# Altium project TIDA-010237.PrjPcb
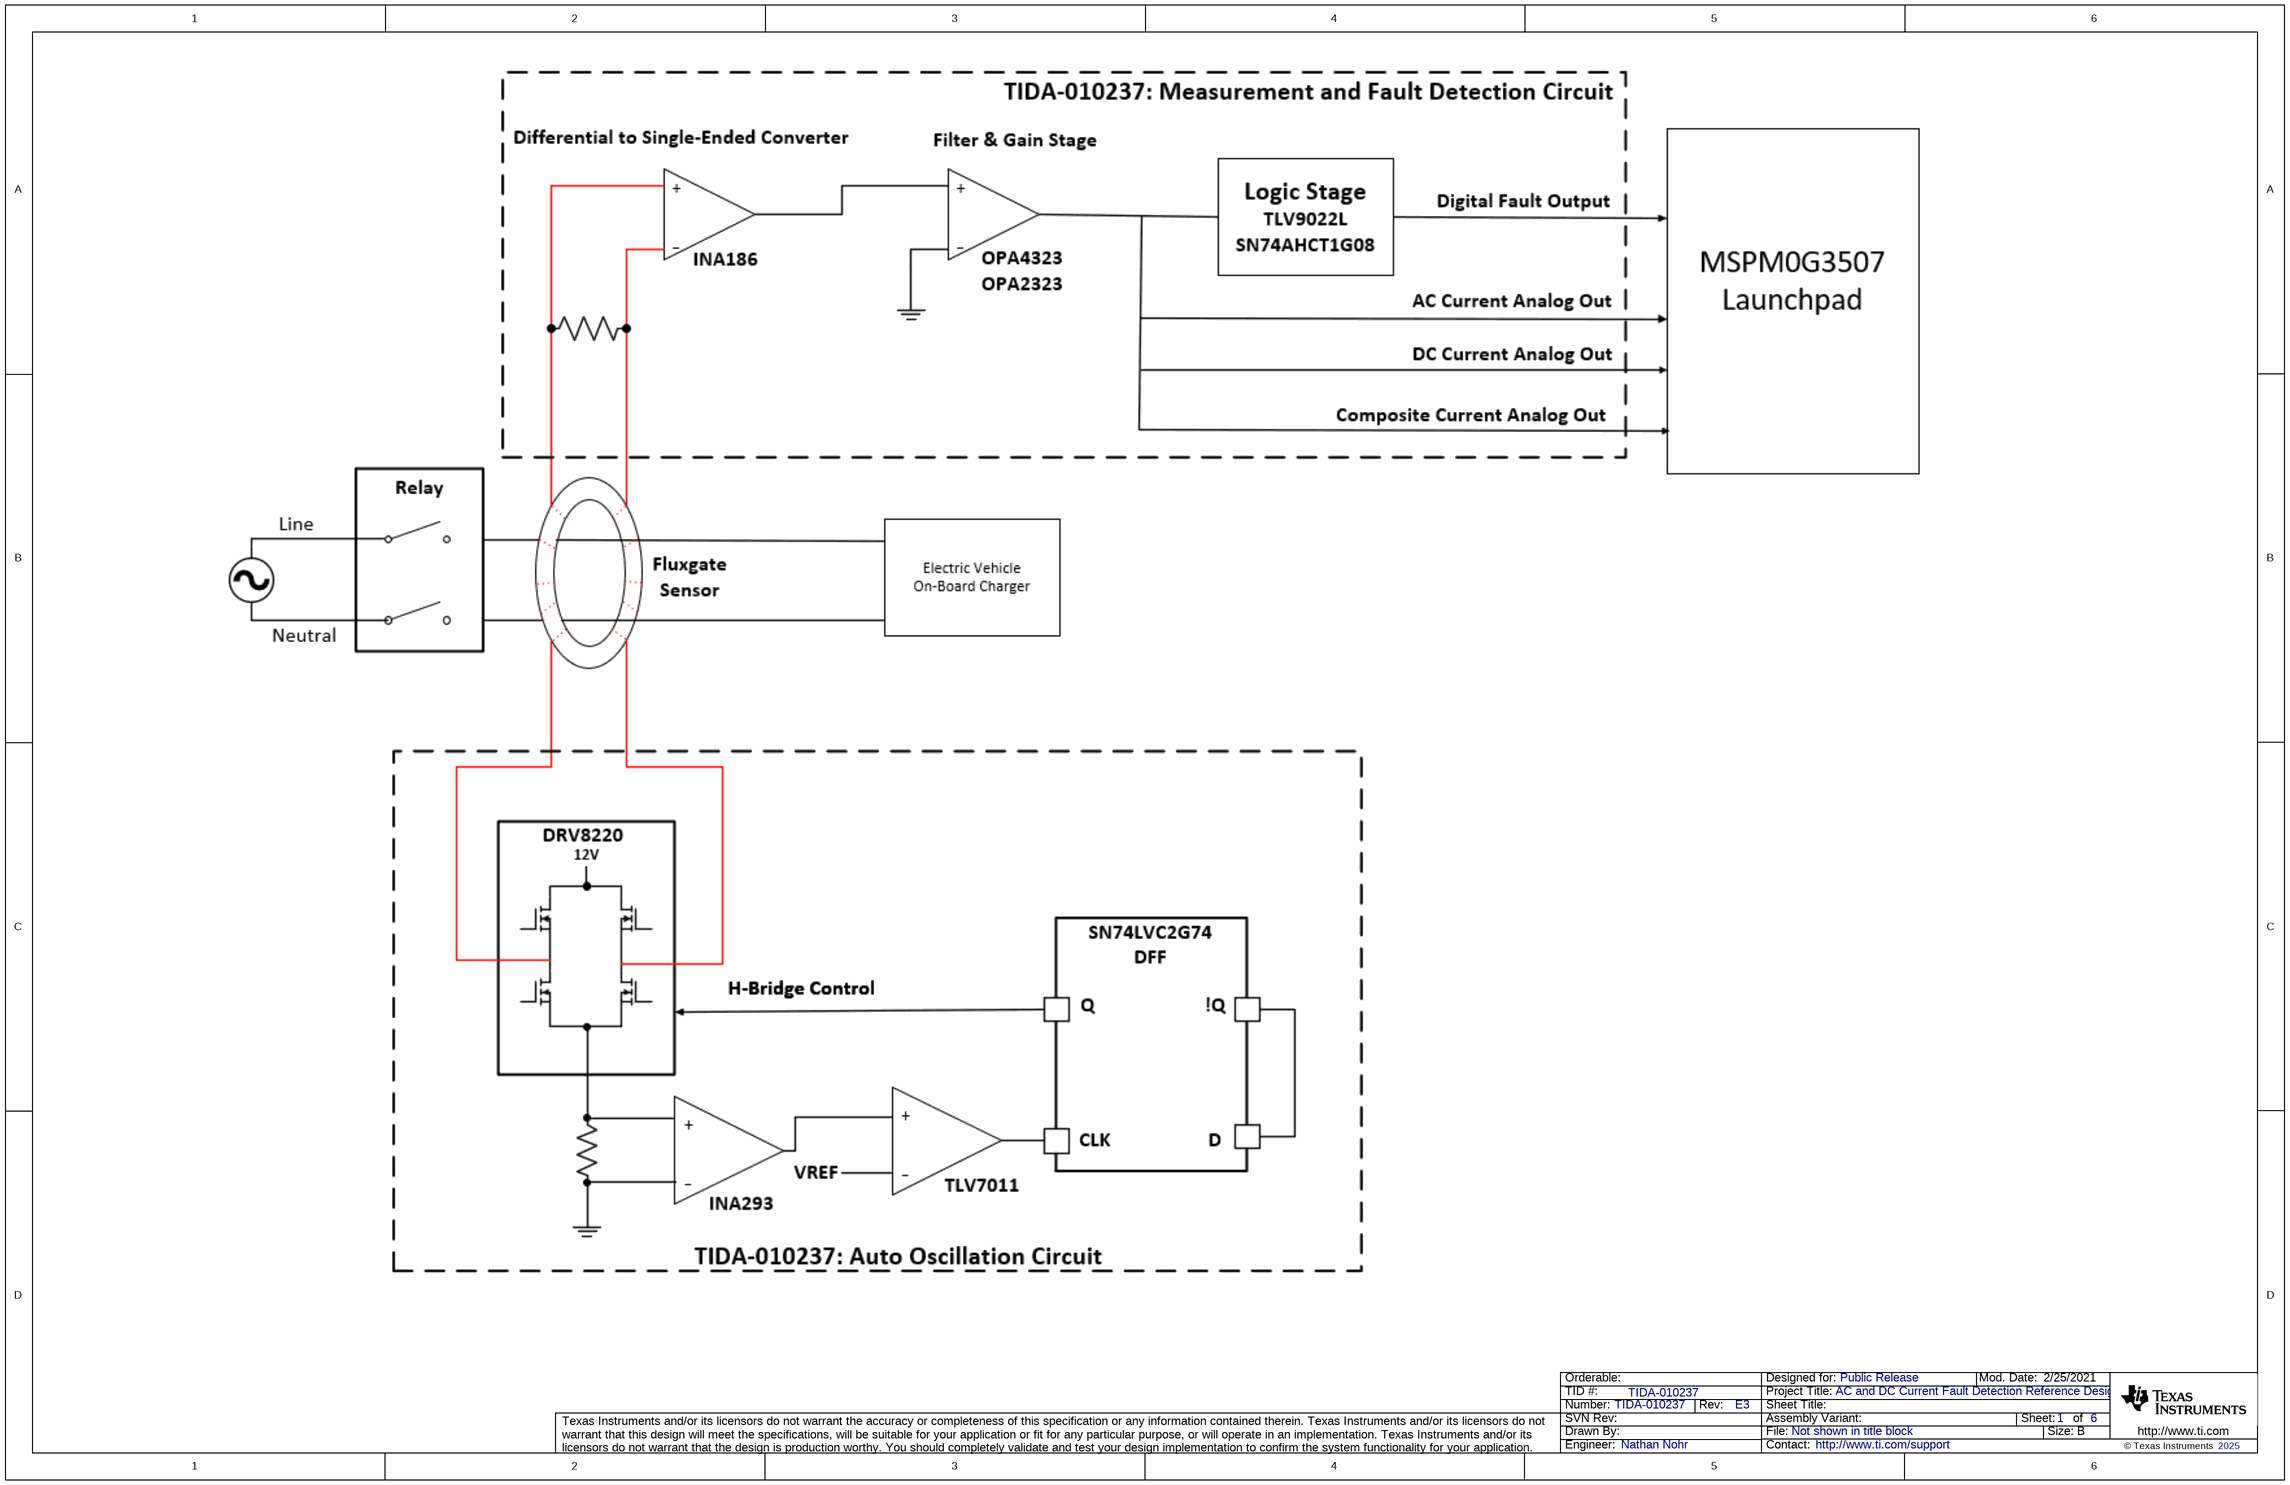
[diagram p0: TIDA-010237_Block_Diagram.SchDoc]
CopyrightYear: 2025; PCB_Layout: Julius Burtell; PCB_Rev: E3; PRJ_Customer: Public Release; PRJ_Engineer: Nathan Nohr; PRJ_Number: TIDA-010237; PRJ_Title: AC and DC Current Fault Detection Reference Design; SCH_Rev: E3; TechSupport: http://www.ti.com/support; TID: TIDA-010237
5 sheets, 144 parts. Net scope: global (net labels, ports and power ports of the same name join across sheets).
Board file: TIDA-010237.PcbDoc
Sheets:
  TIDA-010237_Block_Diagram.SchDoc
  TIDA-010237_Driver_Circuit.SchDoc
  TIDA-010237_Receiver_Circuit.SchDoc
  TIDA-010237_ConnectorsAndPower.SchDoc
  TIDA-010237_Hardware.SchDoc

## Sheet TIDA-010237_Block_Diagram.SchDoc
size 431 x 279 mm; Date: Not shown in title block; ApprovedBy: Not shown in title block; CheckedBy: Not shown in title block; Author: Not shown in title block; CompanyName: Not shown in title block; Engineer: Not shown in title block; Organization: Not shown in title block; Address1: Not shown in title block; Address2: Not shown in title block; Address3: Not shown in title block; Address4: Not shown in title block; DocumentNumber: 1; Revision: Use project parameter SCH_Rev; SheetNumber: 1; SheetTotal: 6; PageSetup: Record=PageOptions¦CenterHorizontal=True¦CenterVertical=True¦PrintScale=1.00¦XCorrection=1.00¦YCorrection=1.00¦PrintKind=0¦BorderSize=5000000¦LeftOffset=0¦BottomOffset=0¦Orientation=2¦PaperLength=1000¦PaperWidth=1000¦Scale=100¦PaperSource=15¦PrintQuality=600¦MediaType=1¦DitherType=10¦PaperKind=Letter¦PrintScaleMode=1

## Sheet TIDA-010237_Driver_Circuit.SchDoc
size 431 x 279 mm; Date: Not shown in title block; ApprovedBy: Not shown in title block; CheckedBy: Not shown in title block; Author: Not shown in title block; CompanyName: Not shown in title block; Engineer: Not shown in title block; Organization: Not shown in title block; Address1: Not shown in title block; Address2: Not shown in title block; Address3: Not shown in title block; Address4: Not shown in title block; DocumentNumber: 2; Revision: Use project parameter SCH_Rev; SheetNumber: 2; SheetTotal: 6; PageSetup: Record=PageOptions¦CenterHorizontal=True¦CenterVertical=True¦PrintScale=1.00¦XCorrection=1.00¦YCorrection=1.00¦PrintKind=0¦BorderSize=5000000¦LeftOffset=0¦BottomOffset=0¦Orientation=2¦PaperLength=1000¦PaperWidth=1000¦Scale=100¦PaperSource=15¦PrintQuality=600¦MediaType=1¦DitherType=10¦PaperKind=Letter¦PrintScaleMode=1
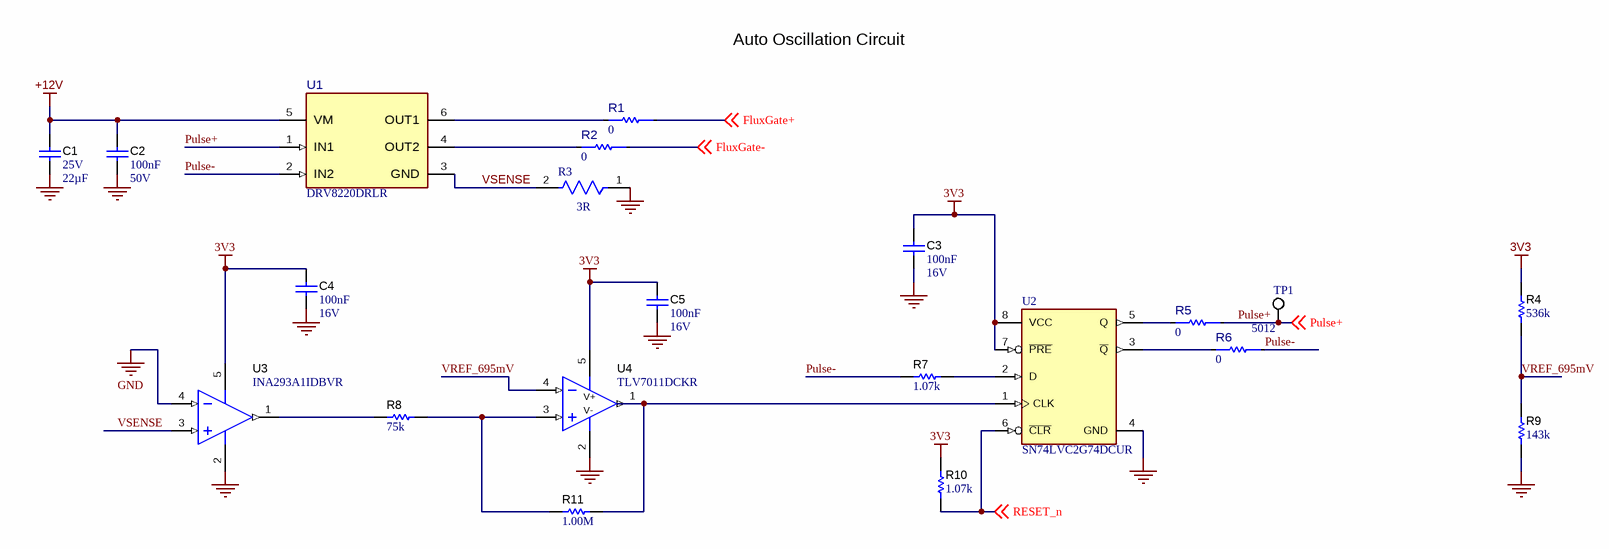
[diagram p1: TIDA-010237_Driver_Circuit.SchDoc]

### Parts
C1  VDC_V: 25V  ValueDisplayed: 22µF  [1210_270]  (hidden comment: CL32B226KAJNFNE)
C2  Cap_F: 100nF  VDC_V: 50V  [0603]  (hidden comment: 06035C104KAZ2A)
C3  Cap_F: 100nF  VDC_V: 16V  [0603]  (hidden comment: EMK107B7104KA-T)
C4  Cap_F: 100nF  VDC_V: 16V  [0603]  (hidden comment: EMK107B7104KA-T)
C5  Cap_F: 100nF  VDC_V: 16V  [0603]  (hidden comment: EMK107B7104KA-T)
R1  value 0  [FP-560112116001_0603-MFG]  (hidden comment: 560112116001)
R2  value 0  [FP-560112116001_0603-MFG]  (hidden comment: 560112116001)
R3  Resistance: 3R  [FP-CRCW1206-e3-IPC_A]  (hidden comment: CRCW12063R00JNEA)
R4  ValueDisplayed: 536k  [0603]  (hidden comment: CRCW0603536KFKEA)
R5  value 0  [FP-560112116001_0603-MFG]  (hidden comment: 560112116001)
R6  value 0  [FP-560112116001_0603-MFG]  (hidden comment: 560112116001)
R7  ValueDisplayed: 1.07k  [0603]  (hidden comment: CRCW06031K07FKEA)
R8  ValueDisplayed: 75k  [0603]  (hidden comment: CRCW060375K0JNEA)
R9  ValueDisplayed: 143k  [0603]  (hidden comment: RC0603FR-07143KL)
R10  ValueDisplayed: 1.07k  [0603]  (hidden comment: CRCW06031K07FKEA)
R11  ValueDisplayed: 1.00M  [0603]  (hidden comment: MCT06030C1004FP500)
TP1  5012  [KSTN-5012_V]
U1  DRV8220DRLR  [DRL0006A-MFG]
U2  SN74LVC2G74DCUR  [FP-DCU0008A-IPC_C]
U3  INA293A1IDBVR  [DBV0005A_M]
U4  TLV7011DCKR  [DCK0005A_N]

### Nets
3V3: C3.1 C4.1 C5.1 R4.2 R10.1 U2.7(~{PRE}) U2.8(VCC) U3.5(V+) U4.5(V+)
+12V: C1.1 C2.1 U1.5(VM)
GND: C1.2 C2.2 C3.2 C4.2 C5.2 R3.1 R9.1 U2.4(GND) U3.2(GND) U3.4(VIN-) U4.2(V-)
FluxGate+: R1.1 ; off-sheet FluxGate+
FluxGate-: R2.1 ; off-sheet FluxGate-
Pulse+: R5.1 TP1.1 U1.1(IN1) ; off-sheet Pulse+
Pulse-: R6.1 R7.1 U1.2(IN2)
RESET_n: R10.2 U2.6(~{CLR}) ; off-sheet RESET_n
VREF_695mV: R4.1 R9.2 U4.4(IN-)
VSENSE: R3.2 U1.3(GND) U3.3(VIN+)
NetR1_2: R1.2 U1.6(OUT1)
NetR2_2: R2.2 U1.4(OUT2)
NetR5_2: R5.2 U2.5(Q)
NetR6_2: R6.2 U2.3(~{Q})
NetR7_2: R7.2 U2.2(D)
NetR8_1: R8.1 U3.1(OUT)
NetR8_2: R8.2 R11.1 U4.3(IN+)
NetR11_2: R11.2 U2.1(CLK) U4.1(OUT)

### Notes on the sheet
- Auto Oscillation Circuit

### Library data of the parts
C1 = CMP-0080066-1: CAP, CERM, 22 µF, 25 V,+/- 10%, X7R, 1210; Manufacturer: Samsung Electro-Mechanics; TaMin_C: -55°C; Polarized: N; SizeAreaWB_mm2: 14.7; U/M: EA; Value: 22uF; TaMax_C: 125°C; SizeZ_mm: 2.7; SizeX_mm: 3.2; SizeY_mm: 2.5; Cap_Case: 1210; SizeArea_mm2: 8; AEC Category: Q200
C2 = CMP-0079095-1: CAP, CERM, 0.1 µF, 50 V,+/- 10%, X7R, AEC-Q200 Grade 1, 0603; Manufacturer: AVX; SizeAreaWB_mm2: 4.68; SizeArea_mm2: 1.28; AEC Qualified: Y; AEC Category: Q200; Value: 0.1uF; TaMax_C: 125°C; SizeZ_mm: 1; Polarized: N; TaMin_C: -55°C; SizeY_mm: 0.8; U/M: EA; SizeX_mm: 1.6; ValueDisplayed: 0.1µF
C3-C5 = CMP-0007119-4: CAP, CERM, 0.1 uF, 16 V, +/- 10%, X7R, 0603; Manufacturer: Taiyo Yuden; TaMin_C: -55°C; Polarized: N; SizeAreaWB_mm2: 4.68; Value1: Unknown; U/M: EA; Value: 0.1uF; TaMax_C: 125°C; SizeZ_mm: 1; SizeX_mm: 1.6; SizeY_mm: 0.8; SizeArea_mm2: 1.28; AEC Category: Q200
R1 R2 R5 R6 = CMP-0125813-1: 0 Ohms Jumper Chip Resistor 0603 (1608 Metric) Anti-Sulfur Thick Film; Manufacturer: Wurth Electronics; AEC Qualified: No; Power_W: 100mW; SizeZ_mm: 0.6mm; Max Current: 1A
R3 = CMP-1014-00013-3: RES Thick Film, 3Ω, 5%, 0.25W, 200ppm/°C, 1206; Voltage Rating (DC): 200V; Power Rating: 250mW
R4 = CMP-0022488-1: RES, 536 k, 1%, 0.1 W, 0603; Manufacturer: Vishay-Dale; Power_W: 100mW; TempCo: 100 ppm/C; U/M: EA; Value: 536k; EIA_Code: E96; SizeX_mm: 1.6; SizeY_mm: 0.8; SizeZ_mm: 1; Value2: 0.1W; SizeArea_mm2: 1.28; VDC_V: 75V; AEC Category: Q200
R7 R10 = CMP-0022112-4: RES, 1.07 k, 1%, 0.1 W, AEC-Q200 Grade 0, 0603; Manufacturer: Vishay-Dale; Power_W: 100mW; TempCo: 100 ppm/C; Value_Code: 1k07; Value: 1.07k; EIA_Code: E96; SizeX_mm: 1.6; SizeY_mm: 0.8; SizeZ_mm: 1; Value2: 0.1W; SizeArea_mm2: 1.28; AEC Qualified: Y; VDC_V: 75V; AEC Category: Q200; AEC Grade: 0
R8 = CMP-0025853-1: RES, 75 k, 5%, 0.1 W, 0603; Manufacturer: Vishay-Dale; Power_W: 100mW; TempCo: 200 ppm/C; Value_Code: 75k0; U/M: EA; Value: 75k; EIA_Code: E24; SizeX_mm: 1.6; SizeY_mm: 0.8; SizeZ_mm: 1; Value2: 0.1W; SizeArea_mm2: 1.28; VDC_V: 75V; AEC Category: Q200
R9 = CMP-0022798-4: RES, 143 k, 1%, 0.1 W, 0603; Manufacturer: Yageo; Power_W: 100mW; TempCo: 100 ppm/C; Value: 143k; EIA_Code: E96; SizeX_mm: 1.6; SizeY_mm: 0.8; SizeZ_mm: 1; Value2: 0.1W; SizeArea_mm2: 1.28; AEC Qualified: N; VDC_V: 75V; AEC Category: Q200; SizeAreaWB_mm2: 4.68
R11 = CMP-0022731-2: RES, 1.00 M, 1%, 0.125 W, 0603; Manufacturer: Vishay/Beyschlag; Power_W: 125mW; TempCo: 50 ppm/C; Value_Code: 1M00; U/M: EA; Value: 1.00Meg; EIA_Code: E96; Res_ohm: 1M; SizeX_mm: 1.6; SizeY_mm: 0.8; SizeZ_mm: 1; Value2: 0.125W; SizeArea_mm2: 1.28; AEC Qualified: N; VDC_V: 75V; AEC Category: Q200
TP1 = CMP-1672-00004-3: Test Point, White, Through Hole, RoHS, Bulk
U1 = CMP-0090278-3: 18V, 1A H-bridge motor driver, PWM, PH/EN, ½ bridge control, with low power sleep mode; Manufacturer: Texas Instruments; TaMax_C: +125°C; Min Supply Voltage: 4.5V; Number Of Outputs: 2; AEC Category: Q200; AEC Qualified: No; SizeZ_mm: 0.6mm; TaMin_C: -40°C; Motor Type: Brushed; CompType: IC; Switching Frequency: 100kHz; Standoff Height: 0mm; TJmax_C: +150°C
U2 = CMP-0859-00648-4: IC FF D-TYPE SNGL 1BIT US8; Manufacturer: Texas Instruments; Frequency: 140MHz; Standoff Height: 0mm; Propagation Delay: 6.1ns; Logic Function Desc: D Type; Number Of Outputs: 2; Nominal Supply Current: 10uA; Max Supply Voltage: 5.5V; Number Of Inputs: 1; Min Supply Voltage: 1.65V
U3 = CMP-0750213-2: INA293 High-Voltage, High Bandwidth, Unidirectional, 110-V Common-Mode, Current-Sense Amplifier, DBV0005A (SOT-23-5); Alternate Manufacturer: Texas Instruments; Alternate PartNumber: INA293A1IDBVT; SizeZ_mm: 1.45; AEC Qualified: N; CompType: IC; SizeAreaWB_mm2: 14.82; SizeArea_mm2: 8.12; SizeY_mm: 2.9; AEC Category: Q200; SizeX_mm: 2.8
U4 = CMP-0860894-1: Low power, small size comparator with push-pull output, DCK0005A (SOT-SC70-5); Alternate Manufacturer: Texas Instruments; Alternate PartNumber: TLV7011DCKT; CompType: IC; SizeZ_mm: 1.1; SizeY_mm: 2; AEC Qualified: N; AEC Category: Q200; SizeX_mm: 2.1; SizeAreaWB_mm2: 9.3; SizeArea_mm2: 4.2; Rating: Catalog

## Sheet TIDA-010237_Receiver_Circuit.SchDoc
size 431 x 279 mm; Date: Not shown in title block; ApprovedBy: Not shown in title block; CheckedBy: Not shown in title block; Author: Not shown in title block; CompanyName: Not shown in title block; Engineer: Not shown in title block; Organization: Not shown in title block; Address1: Not shown in title block; Address2: Not shown in title block; Address3: Not shown in title block; Address4: Not shown in title block; DocumentNumber: 3; Revision: Use project parameter SCH_Rev; SheetNumber: 3; SheetTotal: 6; PageSetup: Record=PageOptions¦CenterHorizontal=True¦CenterVertical=True¦PrintScale=1.00¦XCorrection=1.00¦YCorrection=1.00¦PrintKind=0¦BorderSize=5000000¦LeftOffset=0¦BottomOffset=0¦Orientation=2¦PaperLength=1000¦PaperWidth=1000¦Scale=100¦PaperSource=15¦PrintQuality=600¦MediaType=1¦DitherType=10¦PaperKind=Letter¦PrintScaleMode=1
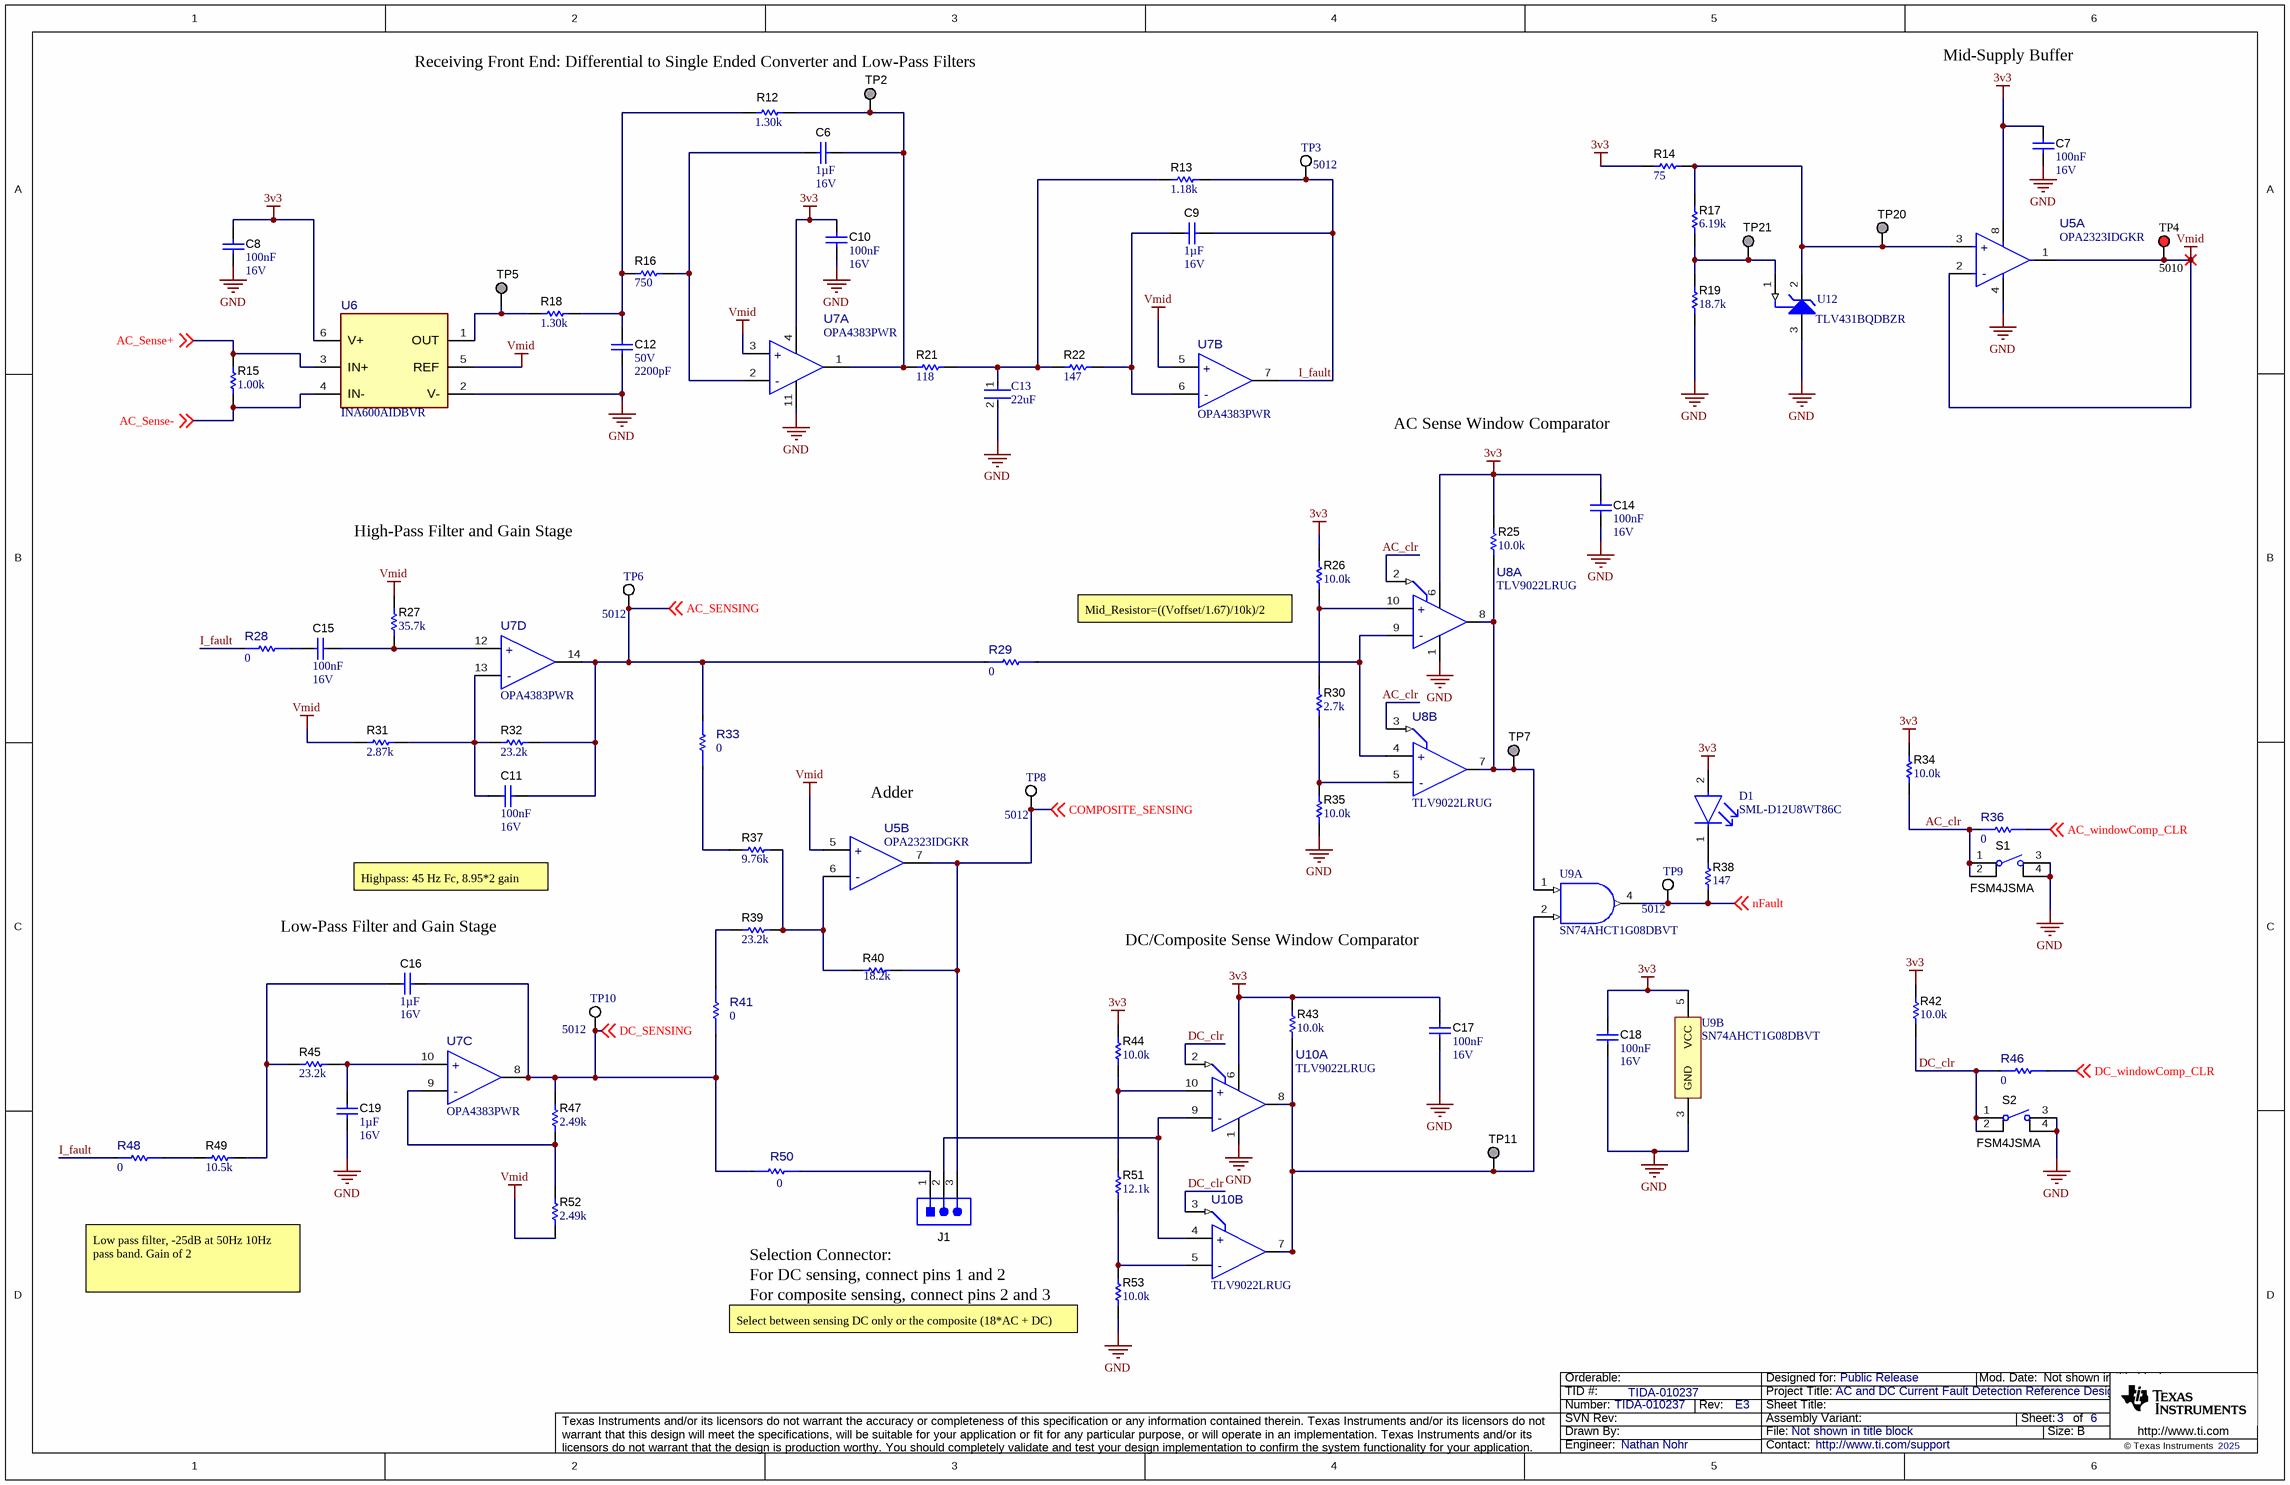
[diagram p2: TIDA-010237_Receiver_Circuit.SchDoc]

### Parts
C6  Cap_F: 1µF  VDC_V: 16V  [0603]  (hidden comment: EMK107B7105KAHT)
C7  Cap_F: 100nF  VDC_V: 16V  [0603]  (hidden comment: EMK107B7104KA-T)
C8  Cap_F: 100nF  VDC_V: 16V  [0603]  (hidden comment: EMK107B7104KA-T)
C9  Cap_F: 1µF  VDC_V: 16V  [0603]  (hidden comment: EMK107B7105KAHT)
C10  Cap_F: 100nF  VDC_V: 16V  [0603]  (hidden comment: EMK107B7104KA-T)
C11  Cap_F: 100nF  VDC_V: 16V  [0603]  (hidden comment: EMK107B7104KA-T)
C12  VDC_V: 50V  ValueDisplayed: 2200pF  [0603]  (hidden comment: GRM1885C1H222JA01D)
C13  Capacitance: 22uF  [FP-1206-L_3_2_0_2-W_1_6_0-IPC_C]  (hidden comment: 1206YD226KAT2A)
C14  Cap_F: 100nF  VDC_V: 16V  [0603]  (hidden comment: EMK107B7104KA-T)
C15  Cap_F: 100nF  VDC_V: 16V  [0603]  (hidden comment: EMK107B7104KA-T)
C16  Cap_F: 1µF  VDC_V: 16V  [0603]  (hidden comment: EMK107B7105KAHT)
C17  Cap_F: 100nF  VDC_V: 16V  [0603]  (hidden comment: EMK107B7104KA-T)
C18  Cap_F: 100nF  VDC_V: 16V  [0603]  (hidden comment: EMK107B7104KA-T)
C19  Cap_F: 1µF  VDC_V: 16V  [0603]  (hidden comment: EMK107B7105KAHT)
D1  SML-D12U8WT86C  [FP-SML-D12-MFG]
J1  PEC03SAAN  [CONN_PEC03SAAN]  (value not drawn)
R12  ValueDisplayed: 1.30k  [0603]  (hidden comment: RC0603FR-071K3L)
R13  ValueDisplayed: 1.18k  [0603]  (hidden comment: CRCW06031K18FKEA)
R14  ValueDisplayed: 75  [0603]  (hidden comment: CRCW060375R0JNEA)
R15  ValueDisplayed: 1.00k  [0603]  (hidden comment: ERA3AEB102V)
R16  ValueDisplayed: 750  [0603]  (hidden comment: CRCW0603750RFKEA)
R17  ValueDisplayed: 6.19k  [0603]  (hidden comment: RT0603BRD076K19L)
R18  ValueDisplayed: 1.30k  [0603]  (hidden comment: RC0603FR-071K3L)
R19  ValueDisplayed: 18.7k  [0603]  (hidden comment: RT0603BRD0718K7L)
R21  ValueDisplayed: 118  [0603]  (hidden comment: RC0603FR-07118RL)
R22  ValueDisplayed: 147  [0603]  (hidden comment: RC0603FR-07147RL)
R25  ValueDisplayed: 10.0k  [0603]  (hidden comment: RC0603FR-0710KL)
R26  ValueDisplayed: 10.0k  [0603]  (hidden comment: RC0603FR-0710KL)
R27  ValueDisplayed: 35.7k  [0603]  (hidden comment: RC0603FR-0735K7L)
R28  value 0  [FP-560112116001_0603-MFG]  (hidden comment: 560112116001)
R29  value 0  [FP-560112116001_0603-MFG]  (hidden comment: 560112116001)
R30  ValueDisplayed: 2.7k  [0603]  (hidden comment: RC0603JR-072K7L)
R31  ValueDisplayed: 2.87k  [0603]  (hidden comment: RC0603FR-072K87L)
R32  ValueDisplayed: 23.2k  [0603]  (hidden comment: CRCW060323K2FKEA)
R33  value 0  [FP-560112116001_0603-MFG]  (hidden comment: 560112116001)
R34  ValueDisplayed: 10.0k  [0603]  (hidden comment: RC0603FR-0710KL)
R35  ValueDisplayed: 10.0k  [0603]  (hidden comment: RC0603FR-0710KL)
R36  value 0  [FP-560112116001_0603-MFG]  (hidden comment: 560112116001)
R37  ValueDisplayed: 9.76k  [0603]  (hidden comment: RC0603FR-079K76L)
R38  ValueDisplayed: 147  [0603]  (hidden comment: RC0603FR-07147RL)
R39  ValueDisplayed: 23.2k  [0603]  (hidden comment: CRCW060323K2FKEA)
R40  ValueDisplayed: 18.2k  [0603]  (hidden comment: RT0603DRE0718K2L)
R41  value 0  [FP-560112116001_0603-MFG]  (hidden comment: 560112116001)
R42  ValueDisplayed: 10.0k  [0603]  (hidden comment: RC0603FR-0710KL)
R43  ValueDisplayed: 10.0k  [0603]  (hidden comment: RC0603FR-0710KL)
R44  ValueDisplayed: 10.0k  [0603]  (hidden comment: RC0603FR-0710KL)
R45  ValueDisplayed: 23.2k  [0603]  (hidden comment: CRCW060323K2FKEA)
R46  value 0  [FP-560112116001_0603-MFG]  (hidden comment: 560112116001)
R47  ValueDisplayed: 2.49k  [0603]  (hidden comment: CRCW06032K49FKEA)
R48  value 0  [FP-560112116001_0603-MFG]  (hidden comment: 560112116001)
R49  ValueDisplayed: 10.5k  [0603]  (hidden comment: CRCW060310K5FKEA)
R50  value 0  [FP-560112116001_0603-MFG]  (hidden comment: 560112116001)
R51  ValueDisplayed: 12.1k  [0603]  (hidden comment: RT0603DRE0712K1L)
R52  ValueDisplayed: 2.49k  [0603]  (hidden comment: CRCW06032K49FKEA)
R53  ValueDisplayed: 10.0k  [0603]  (hidden comment: RC0603FR-0710KL)
S1  FSM4JSMA  [SW_FSM4JSMA]
S2  FSM4JSMA  [SW_FSM4JSMA]
TP2  TP_SM_1MM  [TP_SM_1MM]  (value not drawn)  (no BOM)
TP3  5012  [KSTN-5012_V]
TP4  5010  [KSTN-5010_V]
TP5  TP_SM_1MM  [TP_SM_1MM]  (value not drawn)  (no BOM)
TP6  5012  [KSTN-5012_V]
TP7  TP_SM_1MM  [TP_SM_1MM]  (value not drawn)  (no BOM)
TP8  5012  [KSTN-5012_V]
TP9  5012  [KSTN-5012_V]
TP10  5012  [KSTN-5012_V]
TP11  TP_SM_1MM  [TP_SM_1MM]  (value not drawn)  (no BOM)
TP20  TP_SM_1MM  [TP_SM_1MM]  (value not drawn)  (no BOM)
TP21  TP_SM_1MM  [TP_SM_1MM]  (value not drawn)  (no BOM)
U5  OPA2323IDGKR  [DGK0008A-MFG]  (parts A,B of 2)
U6  INA600AIDBVR  [DBV0006A-MFG]
U7  OPA4383PWR  [PW0014A-MFG]  (parts A,B,C,D of 4)
U8  TLV9022LRUG  [RUG0010A-MFG]  (parts A,B of 2)
U9  SN74AHCT1G08DBVT  [DBV0005A_N]  (parts A,B of 2)
U10  TLV9022LRUG  [RUG0010A-MFG]  (parts A,B of 2)
U12  TLV431BQDBZR  [DBZ0003A_N]

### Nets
3V3: C7.1 C8.1 C10.1 C14.1 C17.1 C18.1 D1.2(A) R14.1 R25.1 R26.1 R34.1 R42.1 R43.1 R44.1 U5.8(V+) U6.6(V+) U7.4(V+) U8.6(V+) U9.5(VCC) U10.6(V+)
GND: C7.2 C8.2 C10.2 C12.2 C13.2 C14.2 C17.2 C18.2 C19.2 R19.1 R35.2 R53.2 S1.3 S1.4 S2.3 S2.4 U5.4(V-) U6.2(V-) U7.11(V-) U8.1(V-) U9.3(GND) U10.1(V-) U12.3(ANODE)
Vmid: R27.2 R31.1 R52.1 TP4.1 U5.1(OUT1) U5.2(IN1-) U5.5(IN2+) U6.5(REF) U7.3(+IN_A) U7.5(+IN_B)
AC_clr: R34.2 R36.2 S1.1 S1.2 U8.2(CLR_A) U8.3(CLR_B)
AC_Sense+: R15.2 U6.3(IN+) ; off-sheet AC_Sense+
AC_Sense-: R15.1 U6.4(IN-) ; off-sheet AC_Sense-
AC_SENSING: C11.2 R29.2 R32.2 R33.2 TP6.1 U7.14(OUT_D) ; off-sheet AC_SENSING
AC_windowComp_CLR: R36.1 ; off-sheet AC_windowComp_CLR
COMPOSITE_SENSING: J1.3 R40.2 TP8.1 U5.7(OUT2) ; off-sheet COMPOSITE_SENSING
DC_clr: R42.2 R46.2 S2.1 S2.2 U10.2(CLR_A) U10.3(CLR_B)
DC_SENSING: C16.2 R41.1 R47.2 R50.2 TP10.1 U7.8(OUT_C) ; off-sheet DC_SENSING
DC_windowComp_CLR: R46.1 ; off-sheet DC_windowComp_CLR
I_fault: C9.1 R13.2 R28.2 R48.2 TP3.1 U7.7(OUT_B)
nFault: R38.1 TP9.1 U9.4(Y) ; off-sheet nFault
NetC6_1: C6.1 R12.2 R21.1 TP2.1 U7.1(OUT_A)
NetC6_2: C6.2 R16.2 U7.2(-IN_A)
NetC9_2: C9.2 R22.2 U7.6(-IN_B)
NetC11_1: C11.1 R31.2 R32.1 U7.13(-IN_D)
NetC12_1: C12.1 R12.1 R16.1 R18.2
NetC13_1: C13.1 R13.1 R21.2 R22.1
NetC15_1: C15.1 R27.1 U7.12(+IN_D)
NetC15_2: C15.2 R28.1
NetC16_1: C16.1 R45.1 R49.2
NetC19_1: C19.1 R45.2 U7.10(+IN_C)
NetD1_1: D1.1(C) R38.2
NetJ1_1: J1.1 R50.1
NetJ1_2: J1.2 U10.4(IN+_B) U10.9(IN-_A)
NetR14_2: R14.2 R17.2 TP20.1 U5.3(IN1+) U12.2(CATHODE)
NetR17_1: R17.1 R19.2 TP21.1 U12.1(REF)
NetR18_1: R18.1 TP5.1 U6.1(OUT)
NetR25_2: R25.2 TP7.1 U8.7(OUT_B) U8.8(OUT_A) U9.1(A)
NetR26_2: R26.2 R30.2 U8.10(IN+_A)
NetR29_1: R29.1 U8.4(IN+_B) U8.9(IN-_A)
NetR30_1: R30.1 R35.1 U8.5(IN-_B)
NetR33_1: R33.1 R37.1
NetR37_2: R37.2 R39.2 R40.1 U5.6(IN2-)
NetR39_1: R39.1 R41.2
NetR43_2: R43.2 TP11.1 U9.2(B) U10.7(OUT_B) U10.8(OUT_A)
NetR44_2: R44.2 R51.2 U10.10(IN+_A)
NetR47_1: R47.1 R52.2 U7.9(-IN_C)
NetR48_1: R48.1 R49.1
NetR51_1: R51.1 R53.1 U10.5(IN-_B)

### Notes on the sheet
- Receiving Front End: Differential to Single Ended Converter and Low-Pass Filters
- Mid-Supply Buffer
- AC Sense Window Comparator
- High-Pass Filter and Gain Stage
- (near R26) Mid_Resistor=((Voffset/1.67)/10k)/2
- (near U5) Adder
- Highpass: 45 Hz Fc, 8.95*2 gain
- (near C16) Low-Pass Filter and Gain Stage
- DC/Composite Sense Window Comparator
- Low pass filter, -25dB at 50Hz 10Hz pass band. Gain of 2
- Selection Connector:
- For DC sensing, connect pins 1 and 2
- (near R53) For composite sensing, connect pins 2 and 3
- (near R53) Select between sensing DC only or the composite (18*AC + DC)

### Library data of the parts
C6 C9 C16 C19 = CMP-0080104-1: CAP, CERM, 1 µF, 16 V,+/- 10%, X7R, AEC-Q200 Grade 1, 0603; Manufacturer: Taiyo Yuden; SizeAreaWB_mm2: 4.68; SizeArea_mm2: 1.28; AEC Qualified: Y; AEC Category: Q200; Value: 1uF; TaMax_C: 125°C; SizeZ_mm: 1; Polarized: N; TaMin_C: -55°C; SizeY_mm: 0.8; U/M: EA; SizeX_mm: 1.6
C7 C8 C10 C11 C14 C15 C17 C18 = CMP-0007119-4: as C3 on sheet TIDA-010237_Driver_Circuit
C12 = CMP-0007198-2: CAP, CERM, 2200 pF, 50 V, +/- 5%, C0G/NP0, 0603; Manufacturer: MuRata; TaMin_C: -55°C; Polarized: N; SizeAreaWB_mm2: 4.68; Value1: Unknown; U/M: EA; Value: 2200pF; TaMax_C: 125°C; SizeZ_mm: 1; SizeX_mm: 1.6; SizeY_mm: 0.8; SizeArea_mm2: 1.28; Cap_F: 2.2nF; AEC Category: Q200
C13 = CMP-1037-04992-2: General Purpose Ceramic Capacitor, 1206, 22uF, 10%, X5R, 15%, 16V
D1 = CMP-08952-000014-1: LED RED 1608 SMD; Manufacturer: Rohm; Reverse Voltage: 5V; Wavelength: 620nm; Luminous Intensity: 63mcd; Automotive Grade: Grade 3; Forward Voltage: 2.2V; Led Orientation: Top View; Forward Current: 20mA; Power Dissipation: 54mW
J1 = CMP-0002338-1: Header, 100mil, 3x1, Tin, TH; Manufacturer: Sullins Connector Solutions; CNHeader: TRUE; Current_A: 3A; Green_Lifecycle: Not Set; Shrouded: N; Gender: Male; Green_REACh: Incomplete; Voltage_V: 1.8kV; Row_Count: 1; Pitch_mm: 2.54; CT: FALSE; Cert_UL: Y
R12 R18 = CMP-0022877-5: RES, 1.30 k, 1%, 0.1 W, 0603; Manufacturer: Yageo; Power_W: 100mW; TempCo: 100 ppm/C; Value_Code: 1k30; Value: 1.30k; EIA_Code: E96; Res_ohm: 1.3k; SizeX_mm: 1.6; SizeY_mm: 0.8; SizeZ_mm: 1; Value2: 0.1W; SizeArea_mm2: 1.28; AEC Qualified: N; VDC_V: 75V; AEC Category: Q200; SizeAreaWB_mm2: 4.68
R13 = CMP-0022116-4: RES, 1.18 k, 1%, 0.1 W, AEC-Q200 Grade 0, 0603; Manufacturer: Vishay-Dale; Power_W: 100mW; TempCo: 100 ppm/C; Value_Code: 1k18; Value: 1.18k; EIA_Code: E96; SizeX_mm: 1.6; SizeY_mm: 0.8; SizeZ_mm: 1; Value2: 0.1W; SizeArea_mm2: 1.28; AEC Qualified: Y; VDC_V: 75V; AEC Category: Q200; AEC Grade: 0
R14 = CMP-0025854-3: RES, 75, 5%, 0.1 W, 0603; Manufacturer: Vishay-Dale; Power_W: 100mW; TempCo: 200 ppm/C; Value_Code: 75R0; U/M: EA; Value: 75; EIA_Code: E24; SizeX_mm: 1.6; SizeY_mm: 0.8; SizeZ_mm: 1; Value2: 0.1W; SizeArea_mm2: 1.28; VDC_V: 75V; AEC Category: Q200
R15 = CMP-0078581-1: RES, 1.00 k, 0.1%, 0.1 W, AEC-Q200 Grade 0, 0603; Manufacturer: Panasonic; Power_W: 100mW; TempCo: 25 ppm/C; Value_Code: 1k00; Value: 1.00k; EIA_Code: E192; Res_ohm: 1k; SizeX_mm: 1.6; SizeY_mm: 0.8; SizeZ_mm: 1; Value2: 0.1W; SizeArea_mm2: 1.28; AEC Qualified: Y; AEC Grade: 0; AEC Category: Q200
R16 = CMP-0022588-5: RES, 750, 1%, 0.1 W, AEC-Q200 Grade 0, 0603; Manufacturer: Vishay-Dale; Power_W: 100mW; TempCo: 100 ppm/C; Value_Code: 750R; Value: 750; EIA_Code: E96; SizeX_mm: 1.6; SizeY_mm: 0.8; SizeZ_mm: 1; Value2: 0.1W; SizeArea_mm2: 1.28; AEC Qualified: Y; VDC_V: 75V; AEC Category: Q200; AEC Grade: 0
R17 = CMP-0024432-2: RES, 6.19 k, 0.1%, 0.1 W, 0603; Manufacturer: Yageo America; Power_W: 100mW; TempCo: 25 ppm/C; Value_Code: 6k19; U/M: EA; Value: 6.19k; EIA_Code: E192; SizeX_mm: 1.6; SizeY_mm: 0.8; SizeZ_mm: 1; Value2: 0.1W; SizeArea_mm2: 1.28; VDC_V: 75V; AEC Category: Q200
R19 = CMP-0023838-3: RES, 18.7 k, 0.1%, 0.1 W, 0603; Manufacturer: Yageo America; Power_W: 100mW; TempCo: 25 ppm/C; Value_Code: 18k7; U/M: EA; Value: 18.7k; EIA_Code: E192; SizeX_mm: 1.6; SizeY_mm: 0.8; SizeZ_mm: 1; Value2: 0.1W; SizeArea_mm2: 1.28; VDC_V: 75V; AEC Category: Q200
R21 = CMP-0022759-5: RES, 118, 1%, 0.1 W, 0603; Manufacturer: Yageo; Power_W: 100mW; TempCo: 100 ppm/C; Value_Code: 118R; Value: 118; EIA_Code: E96; SizeX_mm: 1.6; SizeY_mm: 0.8; SizeZ_mm: 1; Value2: 0.1W; SizeArea_mm2: 1.28; AEC Qualified: N; VDC_V: 75V; AEC Category: Q200; SizeAreaWB_mm2: 4.68
R22 R38 = CMP-0022801-5: RES, 147, 1%, 0.1 W, 0603; Manufacturer: Yageo; Power_W: 100mW; TempCo: 100 ppm/C; Value_Code: 147R; Value: 147; EIA_Code: E96; SizeX_mm: 1.6; SizeY_mm: 0.8; SizeZ_mm: 1; Value2: 0.1W; SizeArea_mm2: 1.28; AEC Qualified: N; VDC_V: 75V; AEC Category: Q200; SizeAreaWB_mm2: 4.68
R25 R26 R34 R35 R42-R44 R53 = CMP-0022746-5: RES, 10.0 k, 1%, 0.1 W, 0603; Manufacturer: Yageo; Power_W: 100mW; TempCo: 100 ppm/C; Value_Code: 10k0; Value: 10.0k; EIA_Code: E96; Res_ohm: 10k; SizeX_mm: 1.6; SizeY_mm: 0.8; SizeZ_mm: 1; Value2: 0.1W; SizeArea_mm2: 1.28; AEC Qualified: N; VDC_V: 75V; AEC Category: Q200; SizeAreaWB_mm2: 4.68
R27 = CMP-0023050-5: RES, 35.7 k, 1%, 0.1 W, 0603; Manufacturer: Yageo; Power_W: 100mW; TempCo: 100 ppm/C; Value_Code: 35k7; Value: 35.7k; EIA_Code: E96; SizeX_mm: 1.6; SizeY_mm: 0.8; SizeZ_mm: 1; Value2: 0.1W; SizeArea_mm2: 1.28; AEC Qualified: N; VDC_V: 75V; AEC Category: Q200; SizeAreaWB_mm2: 4.68
R28 R29 R33 R36 R41 R46 R48 R50 = CMP-0125813-1: as R1 on sheet TIDA-010237_Driver_Circuit
R30 = CMP-0025908-5: RES, 2.7 k, 5%, 0.1 W, 0603; Manufacturer: Yageo; Power_W: 100mW; TempCo: 100 ppm/C; Value_Code: 2k70; Value: 2.7k; EIA_Code: E24; SizeX_mm: 1.6; SizeY_mm: 0.8; SizeZ_mm: 1; Value2: 0.1W; SizeArea_mm2: 1.28; AEC Qualified: N; VDC_V: 75V; AEC Category: Q200; SizeAreaWB_mm2: 4.68
R31 = CMP-0022997-5: RES, 2.87 k, 1%, 0.1 W, 0603; Manufacturer: Yageo; Power_W: 100mW; TempCo: 100 ppm/C; Value_Code: 2k87; Value: 2.87k; EIA_Code: E96; SizeX_mm: 1.6; SizeY_mm: 0.8; SizeZ_mm: 1; Value2: 0.1W; SizeArea_mm2: 1.28; AEC Qualified: N; VDC_V: 75V; AEC Category: Q200; SizeAreaWB_mm2: 4.68
R32 R39 R45 = CMP-0022228-4: RES, 23.2 k, 1%, 0.1 W, AEC-Q200 Grade 0, 0603; Manufacturer: Vishay-Dale; Power_W: 100mW; TempCo: 100 ppm/C; Value_Code: 23k2; Value: 23.2k; EIA_Code: E96; SizeX_mm: 1.6; SizeY_mm: 0.8; SizeZ_mm: 1; Value2: 0.1W; SizeArea_mm2: 1.28; AEC Qualified: Y; VDC_V: 75V; AEC Category: Q200; AEC Grade: 0
R37 = CMP-0023336-5: RES, 9.76 k, 1%, 0.1 W, 0603; Manufacturer: Yageo; Power_W: 100mW; TempCo: 100 ppm/C; Value_Code: 9k76; Value: 9.76k; EIA_Code: E96; SizeX_mm: 1.6; SizeY_mm: 0.8; SizeZ_mm: 1; Value2: 0.1W; SizeArea_mm2: 1.28; AEC Qualified: N; VDC_V: 75V; AEC Category: Q200; SizeAreaWB_mm2: 4.68
R40 = CMP-0024769-3: RES, 18.2 k, 0.5%, 0.1 W, 0603; Manufacturer: Yageo America; Power_W: 100mW; TempCo: 50 ppm/C; Value_Code: 18k2; U/M: EA; Value: 18.2k; EIA_Code: E192; SizeX_mm: 1.6; SizeY_mm: 0.8; SizeZ_mm: 1; Value2: 0.1W; SizeArea_mm2: 1.28; VDC_V: 75V; AEC Category: Q200
R47 R52 = CMP-0022277-4: RES, 2.49 k, 1%, 0.1 W, AEC-Q200 Grade 0, 0603; Manufacturer: Vishay-Dale; Power_W: 100mW; TempCo: 100 ppm/C; Value_Code: 2k49; Value: 2.49k; EIA_Code: E96; SizeX_mm: 1.6; SizeY_mm: 0.8; SizeZ_mm: 1; Value2: 0.1W; SizeArea_mm2: 1.28; AEC Qualified: Y; VDC_V: 75V; AEC Category: Q200; AEC Grade: 0
R49 = CMP-0022000-4: RES, 10.5 k, 1%, 0.1 W, AEC-Q200 Grade 0, 0603; Manufacturer: Vishay-Dale; Power_W: 100mW; TempCo: 100 ppm/C; Value_Code: 10k5; Value: 10.5k; EIA_Code: E96; SizeX_mm: 1.6; SizeY_mm: 0.8; SizeZ_mm: 1; Value2: 0.1W; SizeArea_mm2: 1.28; AEC Qualified: Y; VDC_V: 75V; AEC Category: Q200; AEC Grade: 0
R51 = CMP-0024637-3: RES, 12.1 k, 0.5%, 0.1 W, 0603; Manufacturer: Yageo America; Power_W: 100mW; TempCo: 50 ppm/C; Value_Code: 12k1; U/M: EA; Value: 12.1k; EIA_Code: E192; SizeX_mm: 1.6; SizeY_mm: 0.8; SizeZ_mm: 1; Value2: 0.1W; SizeArea_mm2: 1.28; VDC_V: 75V; AEC Category: Q200
S1 S2 = CMP-0002134-3: Switch, Tactile, SPST-NO, 0.05A, 12V, SMT; Manufacturer: TE Connectivity; CurrentRating_mA: 50A; PositionCount: 1; SwitchFunction: Off-Mom
TP2 TP5 TP7 TP11 TP20 TP21 = CMP-0003825-1: 1mm Test Point, SMT; Manufacturer: Any
TP3 TP6 TP8-TP10 = CMP-1672-00004-3: as TP1 on sheet TIDA-010237_Driver_Circuit
TP4 = CMP-1672-00002-4: Test Point, Red, Through Hole, RoHS, Bulk; Manufacturer: Keystone
U5 = CMP-0127189-1: Dual, 5.5V, 20MHz, zero-cross low-noise (6nV/√Hz) RRIO operational amplifier 8-VSSOP -40 to 125; Manufacturer: Texas Instruments; SizeZ_mm: 1.1mm; AEC Qualified: No; Input Bias Current: 0.5pA; Input Offset Voltage: 0.15mV; Max Dual Supply Voltage: 2.75V; Min Dual Supply Voltage: 850mV; Min Supply Voltage: 1.7V; Nominal Supply Current: 1.6mA; Number Of Channels: 2; Output Current Per Channel: 110mA; Response Time: 250ns; Standoff Height: 0.05mm; TaMax_C: +125°C; TaMin_C: -40°C; TJmax_C: +150°C; Voltage Gain: 120dB
U6 = CMP-0128101-1: 40V, wide common-mode voltage (-40V to 85V) difference amplifier with fixed attenuation ratios 6-SOT-23 -40 to 125; Manufacturer: Texas Instruments; SizeZ_mm: 1.45mm; AEC Qualified: No; Bandwidth: 225kHz; Max Dual Supply Voltage: 20V; Min Dual Supply Voltage: 1.35V; Min Supply Voltage: 2.7V; Number Of Channels: 1; Output Current Per Channel: 50mA; Response Time: 24us; Standoff Height: 0mm; TaMax_C: +150°C; TaMin_C: -55°C
U7 = CMP-0128112-1: Quad, zero-drift, micropower (65μA), high speed-to-power ratio (2.5MHz) RRIO operational amplifier 14-TSSOP -40 to 125; Manufacturer: Texas Instruments; SizeZ_mm: 1.2mm; AEC Qualified: No; Input Bias Current: 10pA; Input Offset Voltage: 0.4uV; Max Dual Supply Voltage: 2.75V; Max Supply Voltage: 5.5V; Min Dual Supply Voltage: 850mV; Min Supply Voltage: 1.7V; Number Of Channels: 4; Output Current Per Channel: 28mA; Response Time: 48us; Standoff Height: 0.05mm; TaMax_C: +125°C; TaMin_C: -40°C; TJmax_C: +150°C; Voltage Gain: 145dB
U8 U10 = CMP-0122167-3: Precision, Self-Latching Comparator; Manufacturer: Texas Instruments; SizeZ_mm: 0.4mm; AEC Qualified: No; Input Bias Current: 0.000005uA; Input Offset Voltage: 0.3mV; Max Supply Voltage: 5.5V; Min Supply Voltage: 1.65V; Nominal Supply Current: 20uA; Number Of Channels: 2; Output Current Per Channel: 100mA; Standoff Height: 0mm; TaMax_C: +125°C; TaMin_C: -40°C; TJmax_C: +150°C; AEC Category: Q200; CompType: IC
U9 = CMP-0051579-2: Single 2-Input Positive-AND Gate, DBV0005A (SOT-23-5); Manufacturer: Texas Instruments; Bits(#): 1; Gate Type: AND; 3-State Output: No; Output Type: CMOS; Logic: True; VCC(Max)(V): 5.5; tpd @ Nom Voltage(Max)(ns): 7.1; Output Drive (IOL/IOH)(Max)(mA): 8/-8; F @ Nom Voltage(Max)(Mhz): 75; VCC(Min)(V): 2; ICC @ Nom Voltage(Max)(mA): 0.01; Voltage(Nom)(V): 5; Rating: Catalog; AEC Category: Q200; AEC Qualified: N; CompType: IC; SizeAreaWB_mm2: 14.82; SizeArea_mm2: 8.12; SizeX_mm: 2.8; SizeY_mm: 2.9; SizeZ_mm: 1.45
U12 = CMP-0033015-1: Low-Voltage Adjustable Precision Shunt Regulator, 15 mA, -40 to 125 degC, 3-pin SOT-23 (DBZ), Green (RoHS & no Sb/Br); Manufacturer: Texas Instruments; VO Adj(Min)(V): 1.24; Iout/Iz(Max)(mA): 15; Rating: Catalog; SubFamily: Shunt Voltage Reference; Initial Accuracy @ 25/deg C(%): 0.5; Temp Coeff(Max)(ppm/ degree C): 129; VO Adj(Max)(V): 6; Min Iz for Regulation(uA): 80

## Sheet TIDA-010237_ConnectorsAndPower.SchDoc
size B; Date: Not shown in title block; ApprovedBy: Not shown in title block; CheckedBy: Not shown in title block; Author: Not shown in title block; CompanyName: Not shown in title block; Engineer: Not shown in title block; Organization: Not shown in title block; Address1: Not shown in title block; Address2: Not shown in title block; Address3: Not shown in title block; Address4: Not shown in title block; DocumentNumber: 5; Revision: Use project parameter SCH_Rev; SheetNumber: 5; SheetTotal: 6; PageSetup: Record=PageOptions¦CenterHorizontal=True¦CenterVertical=True¦PrintScale=1.00¦XCorrection=1.00¦YCorrection=1.00¦PrintKind=0¦BorderSize=5000000¦LeftOffset=0¦BottomOffset=0¦Orientation=2¦PaperLength=1000¦PaperWidth=1000¦Scale=100¦PaperSource=15¦PrintQuality=600¦MediaType=1¦DitherType=10¦PaperKind=Letter¦PrintScaleMode=1
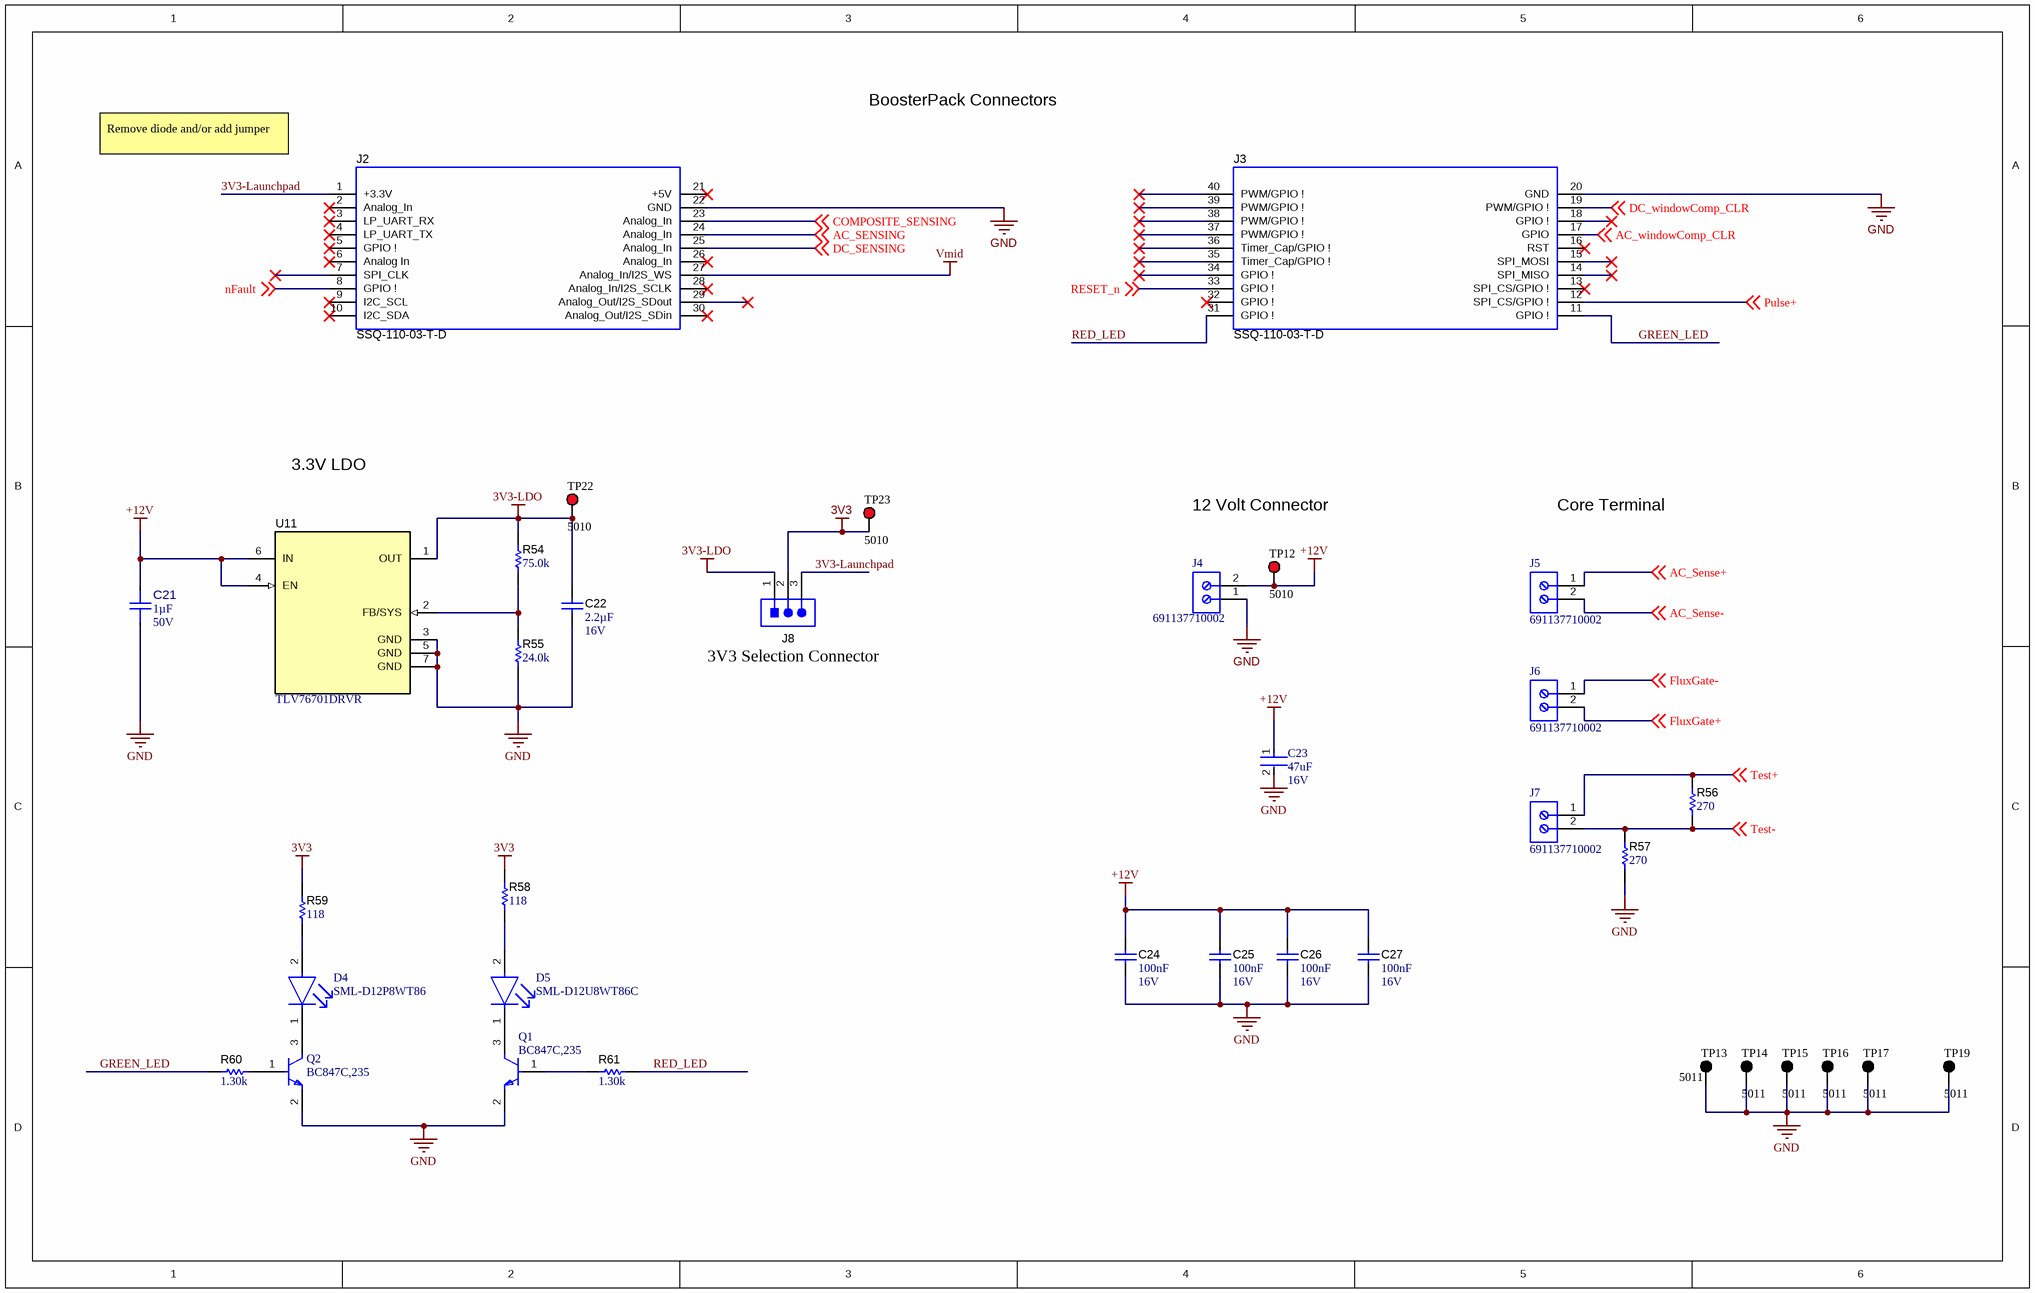
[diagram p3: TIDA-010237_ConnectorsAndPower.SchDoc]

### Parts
C21  Cap_F: 1µF  VDC_V: 50V  [FP-GMC10X7R105K50NT_0603-MFG]  (hidden comment: GMC10X7R105K50NT)
C22  Cap_F: 2.2µF  VDC_V: 16V  [0603]  (hidden comment: EMK107BB7225MA-T)
C23  Capacitance: 47uF  Voltage Rating (DC): 16V  [FP-GRM32E-0_3-0_2-IPC_A]  (hidden comment: GRM32EC81C476KE15K)
C24  Cap_F: 100nF  VDC_V: 16V  [0603]  (hidden comment: EMK107B7104KA-T)
C25  Cap_F: 100nF  VDC_V: 16V  [0603]  (hidden comment: EMK107B7104KA-T)
C26  Cap_F: 100nF  VDC_V: 16V  [0603]  (hidden comment: EMK107B7104KA-T)
C27  Cap_F: 100nF  VDC_V: 16V  [0603]  (hidden comment: EMK107B7104KA-T)
D4  SML-D12P8WT86  [FP-SML-D12-MFG]
D5  SML-D12U8WT86C  [FP-SML-D12-MFG]
J2  SSQ-110-03-T-D  [BoosterPack_40pin_J1J3]
J3  SSQ-110-03-T-D  [BoosterPack_40pin_J2J4]
J4  691137710002  [691137710002]
J5  691137710002  [691137710002]
J6  691137710002  [691137710002]
J7  691137710002  [691137710002]
J8  PEC03SAAN  [CONN_PEC03SAAN]  (value not drawn)
Q1  BC847C,235  [FP-SOT23-MFG]
Q2  BC847C,235  [FP-SOT23-MFG]
R54  ValueDisplayed: 75.0k  [0603]  (hidden comment: RC0603FR-0775KL)
R55  ValueDisplayed: 24.0k  [0603]  (hidden comment: RC0603FR-0724KL)
R56  ValueDisplayed: 270  [0603]  (hidden comment: RC0603JR-07270RL)
R57  ValueDisplayed: 270  [0603]  (hidden comment: RC0603JR-07270RL)
R58  ValueDisplayed: 118  [0603]  (hidden comment: RC0603FR-07118RL)
R59  ValueDisplayed: 118  [0603]  (hidden comment: RC0603FR-07118RL)
R60  ValueDisplayed: 1.30k  [0603]  (hidden comment: RC0603FR-071K3L)
R61  ValueDisplayed: 1.30k  [0603]  (hidden comment: RC0603FR-071K3L)
TP12  5010  [KSTN-5010_V]
TP13  5011  [KSTN-5011_V]
TP14  5011  [KSTN-5011_V]
TP15  5011  [KSTN-5011_V]
TP16  5011  [KSTN-5011_V]
TP17  5011  [KSTN-5011_V]
TP19  5011  [KSTN-5011_V]
TP22  5010  [KSTN-5010_V]
TP23  5010  [KSTN-5010_V]
U11  TLV76701DRVR  [DRV0006A]

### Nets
3V3: J8.2 R58.2 R59.2 TP23.1
3V3-LDO: C22.1 J8.1 R54.2 TP22.1 U11.1(OUT)
+12V: C21.2 C23.1 C24.1 C25.1 C26.1 C27.1 J4.2 TP12.1 U11.4(EN) U11.6(IN)
GND: C21.1 C22.2 C23.2 C24.2 C25.2 C26.2 C27.2 J2.22(GND) J3.20(GND) J4.1 Q1.2(E) Q2.2(E) R55.1 R57.1 TP13.1 TP14.1 TP15.1 TP16.1 TP17.1 TP19.1 U11.3(GND) U11.5(GND) U11.7(GND)
Vmid: J2.27(Analog_In/I2S_WS)
3V3-Launchpad: J2.1(+3.3V) J8.3
AC_Sense+: J5.1 ; off-sheet AC_Sense+
AC_Sense-: J5.2 ; off-sheet AC_Sense-
AC_SENSING: J2.24(Analog_In) ; off-sheet AC_SENSING
AC_windowComp_CLR: J3.17(GPIO) ; off-sheet AC_windowComp_CLR
COMPOSITE_SENSING: J2.23(Analog_In) ; off-sheet COMPOSITE_SENSING
DC_SENSING: J2.25(Analog_In) ; off-sheet DC_SENSING
DC_windowComp_CLR: J3.19(PWM/GPIO_!) ; off-sheet DC_windowComp_CLR
FluxGate+: J6.2 ; off-sheet FluxGate+
FluxGate-: J6.1 ; off-sheet FluxGate-
GREEN_LED: J3.11(GPIO_!) R60.2
nFault: J2.8(GPIO_!) ; off-sheet nFault
Pulse+: J3.12(SPI_CS/GPIO_!) ; off-sheet Pulse+
RED_LED: J3.31(GPIO_!) R61.1
RESET_n: J3.33(GPIO_!) ; off-sheet RESET_n
Test+: J7.1 R56.2 ; off-sheet Test+
Test-: J7.2 R56.1 R57.2 ; off-sheet Test-
NetD4_1: D4.1(C) Q2.3(C)
NetD4_2: D4.2(A) R59.1
NetD5_1: D5.1(C) Q1.3(C)
NetD5_2: D5.2(A) R58.1
NetQ1_1: Q1.1(B) R61.2
NetQ2_1: Q2.1(B) R60.1
NetR54_1: R54.1 R55.2 U11.2(FB/SYS)

Not connected (* = marked no-connect by the designer): J2 2(Analog_In)* 3(LP_UART_RX)* 4(LP_UART_TX)* 5(GPIO_!)* 6(Analog_In)* 7(SPI_CLK)* 9(I2C_SCL)* 10(I2C_SDA)* 21(+5V)* 26(Analog_In)* 28(Analog_In/I2S_SCLK)* 29(Analog_Out/I2S_SDout)* 30(Analog_Out/I2S_SDin)*; J3 13(SPI_CS/GPIO_!)* 14(SPI_MISO)* 15(SPI_MOSI)* 16(RST)* 18(GPIO_!)* 32(GPIO_!)* 34(GPIO_!)* 35(Timer_Cap/GPIO_!)* 36(Timer_Cap/GPIO_!)* 37(PWM/GPIO_!)* 38(PWM/GPIO_!)* 39(PWM/GPIO_!)* 40(PWM/GPIO_!)*

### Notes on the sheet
- BoosterPack Connectors
- Remove diode and/or add jumper
- 3.3V LDO
- 12 Volt Connector
- Core Terminal
- (near J8) 3V3 Selection Connector

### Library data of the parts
C21 = CMP-0095295-1: 1 µF ±10% 50V Ceramic Capacitor X7R 0603 (1608 Metric); Manufacturer: Cal-Chip Electronics; SizeZ_mm: 1mm; ValueDisplayed: 1uF; Value: 1µF; AEC Qualified: No; TempCo: 30ppm/°C
C22 = CMP-0064934-3: CAP, CERM, 2.2 uF, 16 V,+/- 10%, X7R, 0603; Manufacturer: Taiyo Yuden; TaMin_C: -55°C; Polarized: N; SizeAreaWB_mm2: 4.68; Value1: Unknown; U/M: EA; Value: 2.2uF; TaMax_C: 125°C; SizeZ_mm: 1; SizeX_mm: 1.6; SizeY_mm: 0.8; SizeArea_mm2: 1.28; AEC Category: Q200
C23 = CMP-06035-017875-1: Chip Multilayer Ceramic Capacitors for General Purpose, 1210, 47uF, X6S, 22%, 10%, 16V
C24-C27 = CMP-0007119-4: as C3 on sheet TIDA-010237_Driver_Circuit
D4 = CMP-08952-000019-1: LED GREEN DIFFUSED 0603 SMD; Manufacturer: Rohm; Forward Current: 20mA; Luminous Intensity: 6.3mcd; Led Orientation: Top View; Forward Voltage: 2.2V; Power Dissipation: 54mW; Reverse Voltage: 5V; Wavelength: 560nm
D5 = CMP-08952-000014-1: as D1 on sheet TIDA-010237_Receiver_Circuit
J2 = CMP-0003837-4: Receptacle, 2.54mm, 10x2, Tin, TH; Alternate PartNumber: CRD-081413-A-G; Manufacturer: Samtec; Alternate Manufacturer: Major League Electronics; Note: Booster Pack 40 pin J1 and J3; Green_Lifecycle: Active; Green_REACh: Incomplete
J3 = CMP-0078266-4: Receptacle, 2.54mm, 10x2, Tin, TH; Alternate PartNumber: CRD-081413-A-G; Manufacturer: Samtec; Alternate Manufacturer: Major League Electronics; Note: Booster Pack 40 pin J2 and J4; Green_REACh: Incomplete; Green_Lifecycle: Active
J4-J7 = CMP-1502-03324-2: NexarPartId: 78871135; Voltage Rating: 300V; Number of Contacts: 2; Current Rating: 16A
J8 = CMP-0002338-1: as J1 on sheet TIDA-010237_Receiver_Circuit
Q1 Q2 = CMP-14406-000033-1: TRANS NPN 45V 100MA TO236AB
R54 = CMP-0023267-5: RES, 75.0 k, 1%, 0.1 W, 0603; Manufacturer: Yageo; Power_W: 100mW; TempCo: 100 ppm/C; Value_Code: 75k0; Value: 75.0k; EIA_Code: E96; Res_ohm: 75k; SizeX_mm: 1.6; SizeY_mm: 0.8; SizeZ_mm: 1; Value2: 0.1W; SizeArea_mm2: 1.28; AEC Qualified: N; VDC_V: 75V; AEC Category: Q200; SizeAreaWB_mm2: 4.68
R55 = CMP-0022945-5: RES, 24.0 k, 1%, 0.1 W, 0603; Manufacturer: Yageo; Power_W: 100mW; TempCo: 100 ppm/C; Value_Code: 24k0; Value: 24.0k; Res_ohm: 24k; SizeX_mm: 1.6; SizeY_mm: 0.8; SizeZ_mm: 1; Value2: 0.1W; SizeArea_mm2: 1.28; AEC Qualified: N; VDC_V: 75V; AEC Category: Q200; SizeAreaWB_mm2: 4.68
R56 R57 = CMP-0025904-5: RES, 270, 5%, 0.1 W, 0603; Manufacturer: Yageo; Power_W: 100mW; TempCo: 100 ppm/C; Value_Code: 270R; Value: 270; EIA_Code: E24; SizeX_mm: 1.6; SizeY_mm: 0.8; SizeZ_mm: 1; Value2: 0.1W; SizeArea_mm2: 1.28; AEC Qualified: N; VDC_V: 75V; AEC Category: Q200; SizeAreaWB_mm2: 4.68
R58 R59 = CMP-0022759-5: as R21 on sheet TIDA-010237_Receiver_Circuit
R60 R61 = CMP-0022877-5: as R12 on sheet TIDA-010237_Receiver_Circuit
TP12 TP22 TP23 = CMP-1672-00002-4: as TP4 on sheet TIDA-010237_Receiver_Circuit
TP13-TP17 TP19 = CMP-1672-00003-4: Test Point, Black, Through Hole, RoHS, Bulk; Manufacturer: Keystone
U11 = CMP-0079546-2: 1-A, Positive Voltage Regulator, DRV0006A (WSON-6); Alternate Manufacturer: Texas Instruments; SizeY_mm: 2; SizeZ_mm: 0.8; CompType: IC; AEC Qualified: N; SizeArea_mm2: 4; AEC Category: Q200; SizeAreaWB_mm2: 9

## Sheet TIDA-010237_Hardware.SchDoc
size 431 x 279 mm; Date: Not shown in title block; ApprovedBy: Not shown in title block; CheckedBy: Not shown in title block; Author: Not shown in title block; CompanyName: Not shown in title block; Engineer: Not shown in title block; Organization: Not shown in title block; Address1: Not shown in title block; Address2: Not shown in title block; Address3: Not shown in title block; Address4: Not shown in title block; DocumentNumber: 6; Revision: Use project parameter SCH_Rev; SheetNumber: 6; SheetTotal: 6; PageSetup: Record=PageOptions¦CenterHorizontal=True¦CenterVertical=True¦PrintScale=1.00¦XCorrection=1.00¦YCorrection=1.00¦PrintKind=0¦BorderSize=5000000¦LeftOffset=0¦BottomOffset=0¦Orientation=2¦PaperLength=1000¦PaperWidth=1000¦Scale=100¦PaperSource=15¦PrintQuality=600¦MediaType=1¦DitherType=10¦PaperKind=Letter¦PrintScaleMode=1
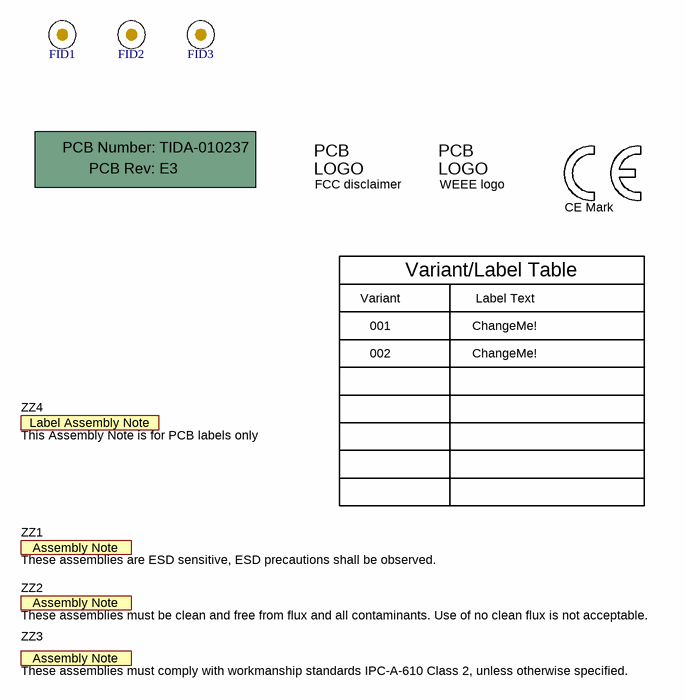
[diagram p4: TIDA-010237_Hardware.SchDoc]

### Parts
!PCB1  Printed Circuit Board  (value not drawn)  (mechanical)
FID1  Fiducial  [Fiducial10-20]  (value not drawn)
FID2  Fiducial  [Fiducial10-20]  (value not drawn)
FID3  Fiducial  [Fiducial10-20]  (value not drawn)
Logo1  FCC disclaimer  [FCC_disclaimer]  (no BOM)
Logo2  WEEE logo  [WEEE_Minimum]  (no BOM)
LOGO3  CE Mark  [CE_Mark_5mm]  (no BOM)
ZZ1  These assemblies are ESD sensitive, ESD precautions shall be observed.  [AssemblyNote]  (no BOM)
ZZ2  These assemblies must be clean and free from flux and all contaminants. Use of no clean flux is not acceptable.  [AssemblyNote]  (no BOM)
ZZ3  These assemblies must comply with workmanship standards IPC-A-610 Class 2, unless otherwise specified.  [AssemblyNote]  (no BOM)
ZZ4  This Assembly Note is for PCB labels only  [AssemblyNoteLabel]  (no BOM)

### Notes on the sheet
- Variant
- Variant/Label Table
- Label Text
- 001
- 002
- ChangeMe!

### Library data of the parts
!PCB1 = CMP-0003618-2: Manufacturer: Any; PartNumber: TIDA-010237
FID1-FID3 = CMP-0077181-1: Fiducial mark.  There is nothing to buy or mount.
Logo1 = CMP-0074847-1: FCC_disclaimer
Logo2 = CMP-0074769-4: Manufacturer: Texas Instruments; CompType: IC; AEC Category: Q200
LOGO3 = CMP-0074844-2: Manufacturer: Texas Instruments; SymbolCreator: a0412235; AEC Category: Q200; CompType: IC
ZZ1 = CMP-0077236-1
ZZ2 = CMP-0077237-1
ZZ3 = CMP-0077238-1
ZZ4 = CMP-0003616-3

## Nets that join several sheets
3V3: TIDA-010237_Driver_Circuit (9 pins), TIDA-010237_Receiver_Circuit (20 pins), TIDA-010237_ConnectorsAndPower (J8.2 R58.2 R59.2 TP23.1)
+12V: TIDA-010237_Driver_Circuit (C1.1 C2.1 U1.5), TIDA-010237_ConnectorsAndPower (10 pins)
GND: TIDA-010237_Driver_Circuit (11 pins), TIDA-010237_Receiver_Circuit (23 pins), TIDA-010237_ConnectorsAndPower (23 pins)
Vmid: TIDA-010237_Receiver_Circuit (10 pins), TIDA-010237_ConnectorsAndPower (J2.27)
AC_Sense+: TIDA-010237_Receiver_Circuit (R15.2 U6.3), TIDA-010237_ConnectorsAndPower (J5.1)
AC_Sense-: TIDA-010237_Receiver_Circuit (R15.1 U6.4), TIDA-010237_ConnectorsAndPower (J5.2)
AC_SENSING: TIDA-010237_Receiver_Circuit (6 pins), TIDA-010237_ConnectorsAndPower (J2.24)
AC_windowComp_CLR: TIDA-010237_Receiver_Circuit (R36.1), TIDA-010237_ConnectorsAndPower (J3.17)
COMPOSITE_SENSING: TIDA-010237_Receiver_Circuit (J1.3 R40.2 TP8.1 U5.7), TIDA-010237_ConnectorsAndPower (J2.23)
DC_SENSING: TIDA-010237_Receiver_Circuit (6 pins), TIDA-010237_ConnectorsAndPower (J2.25)
DC_windowComp_CLR: TIDA-010237_Receiver_Circuit (R46.1), TIDA-010237_ConnectorsAndPower (J3.19)
FluxGate+: TIDA-010237_Driver_Circuit (R1.1), TIDA-010237_ConnectorsAndPower (J6.2)
FluxGate-: TIDA-010237_Driver_Circuit (R2.1), TIDA-010237_ConnectorsAndPower (J6.1)
nFault: TIDA-010237_Receiver_Circuit (R38.1 TP9.1 U9.4), TIDA-010237_ConnectorsAndPower (J2.8)
Pulse+: TIDA-010237_Driver_Circuit (R5.1 TP1.1 U1.1), TIDA-010237_ConnectorsAndPower (J3.12)
RESET_n: TIDA-010237_Driver_Circuit (R10.2 U2.6), TIDA-010237_ConnectorsAndPower (J3.33)

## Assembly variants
001: not fitted FID1 FID2 FID3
